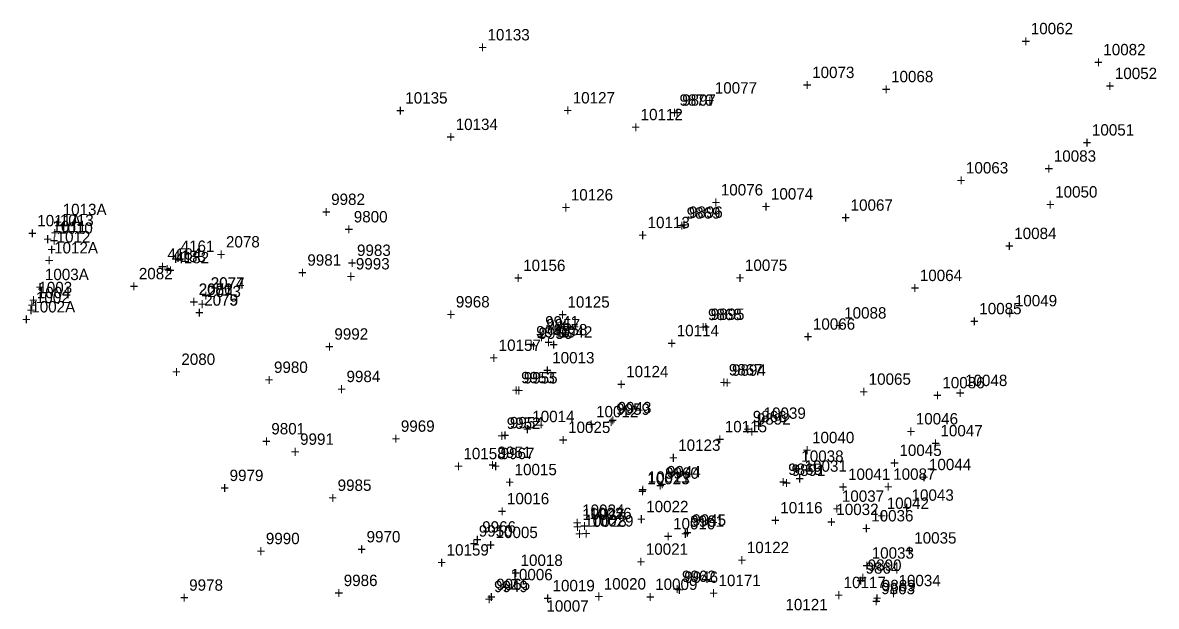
# Model space of a CAD drawing. Extents: x 1136220 to 1137808, y 528804 to 531215.
# Drawn here: x 1137114.7 to 1137364.2, y 528944.9 to 529073.3 of the extents above; entities that cross this region are included whole.
import ezdxf

# ---------------------------------------------------------------- set-up
doc = ezdxf.new("R2010")
doc.units = 0
for name, color, linetype in [('S_Annotation_Label', 7, 'Continuous'), ('S_Curb_Type_3', 7, 'Continuous'), ('S_Drainage_Culvert_Top', 7, 'Continuous'), ('S_Drainage_Invert', 7, 'Continuous'), ('S_Drainage_Sump', 7, 'Continuous'), ('S_Ground_Elevation', 7, 'Continuous'), ('S_Ground_LevelString', 7, 'Continuous'), ('S_Misc_MiscItems', 7, 'Continuous'), ('S_Property_ConcPad', 7, 'Continuous'), ('S_Roadway_Edge_Pavement', 7, 'Continuous'), ('S_Utilities_UG_Sanitary_MH', 7, 'Continuous'), ('S_Utilities_UG_Water_Gate', 7, 'Continuous'), ('S_Utilities_UG_Water_Line', 7, 'Continuous')]:
    doc.layers.add(name, color=color, linetype=linetype)

msp = doc.modelspace()

# ---------------------------------------------------------------- texts
at = {"layer": 'S_Annotation_Label'}
for s, p in [('9800', (1137187.58, 529029.39)), ('+', (1137185.52, 529026.64)), ('10088', (1137295.52, 529008.24)), ('+', (1137293.46, 529005.49)), ('9801', (1137169.43, 528982.76)), ('+', (1137167.37, 528980.01))]:
    msp.add_text(s, height=2.5, dxfattribs=at).set_placement(p)
at = {"layer": 'S_Curb_Type_3'}
for s, p in [('9897', (1137259.85, 529055.06)), ('+', (1137257.79, 529052.31)), ('9896', (1137261.36, 529030.4)), ('+', (1137259.29, 529027.65)), ('9895', (1137266.13, 529007.94)), ('9957', (1137229.96, 529005.67)), ('9958', (1137231.54, 529004.54)), ('+', (1137264.07, 529005.19)), ('+', (1137227.9, 529002.92)), ('9956', (1137228.25, 529003.77)), ('+', (1137226.18, 529001.02)), ('+', (1137229.48, 529001.79)), ('9894', (1137270.84, 528995.66)), ('9955', (1137225, 528993.96)), ('+', (1137268.78, 528992.91)), ('+', (1137222.94, 528991.21)), ('9959', (1137245.34, 528987.06)), ('9892', (1137276.3, 528984.9)), ('9954', (1137221.95, 528984.1)), ('+', (1137243.28, 528984.31)), ('+', (1137219.89, 528981.36)), ('+', (1137274.24, 528982.15)), ('9967', (1137219.9, 528977.32)), ('+', (1137217.84, 528974.57)), ('9960', (1137256.11, 528973.01)), ('9891', (1137283.93, 528973.63)), ('+', (1137254.05, 528970.26)), ('+', (1137281.87, 528970.88)), ('9961', (1137261.64, 528962.44)), ('9966', (1137215.85, 528961.16)), ('+', (1137213.79, 528958.41)), ('+', (1137259.58, 528959.69)), ('9890', (1137300.7, 528952.76)), ('9962', (1137259.82, 528950.3)), ('+', (1137298.63, 528950.01)), ('9965', (1137218.94, 528948.52)), ('+', (1137257.76, 528947.55)), ('9889', (1137303.82, 528948.27)), ('+', (1137216.88, 528945.77)), ('+', (1137301.76, 528945.52))]:
    msp.add_text(s, height=2.5, dxfattribs=at).set_placement(p)
at = {"layer": 'S_Drainage_Culvert_Top'}
for s, p in [('1013A', (1137123.51, 529030.99)), ('1011A', (1137117.91, 529028.53)), ('+', (1137121.45, 529028.24)), ('+', (1137115.85, 529025.78)), ('1012A', (1137121.62, 529022.57)), ('2078', (1137159.45, 529023.88)), ('+', (1137157.39, 529021.13)), ('+', (1137119.56, 529019.82)), ('1003A', (1137119.6, 529016.7)), ('2082', (1137140.27, 529016.88)), ('2077', (1137156.11, 529014.8)), ('+', (1137117.54, 529013.95)), ('+', (1137138.21, 529014.13)), ('2081', (1137153.47, 529013.43)), ('1002A', (1137116.6, 529009.59)), ('+', (1137151.41, 529010.68)), ('+', (1137154.05, 529012.05)), ('2079', (1137154.67, 529011.08)), ('+', (1137152.61, 529008.33)), ('+', (1137114.54, 529006.84)), ('2080', (1137149.63, 528998.05)), ('+', (1137147.57, 528995.3))]:
    msp.add_text(s, height=2.5, dxfattribs=at).set_placement(p)
at = {"layer": 'S_Drainage_Invert'}
for s, p in [('1011', (1137121.28, 529027.25)), ('1013', (1137122.89, 529028.63)), ('+', (1137120.83, 529025.88)), ('1012', (1137122.17, 529024.96)), ('+', (1137119.22, 529024.5)), ('+', (1137120.11, 529022.21)), ('2074', (1137156.08, 529014.83)), ('1003', (1137118.16, 529013.82)), ('2076', (1137153.44, 529013.47)), ('+', (1137116.1, 529011.07)), ('1002', (1137117.61, 529011.63)), ('+', (1137151.38, 529010.72)), ('+', (1137154.02, 529012.08)), ('2075', (1137154.65, 529011.07)), ('+', (1137115.55, 529008.88)), ('+', (1137152.59, 529008.32))]:
    msp.add_text(s, height=2.5, dxfattribs=at).set_placement(p)
at = {"layer": 'S_Drainage_Sump'}
for s, p in [('1010', (1137122.7, 529026.9)), ('+', (1137120.64, 529024.15)), ('1004', (1137117.82, 529012.72)), ('+', (1137115.76, 529009.97))]:
    msp.add_text(s, height=2.5, dxfattribs=at).set_placement(p)
at = {"layer": 'S_Ground_Elevation'}
for s, p in [('10062', (1137336.59, 529070.78)), ('+', (1137334.53, 529068.03)), ('10073', (1137288.47, 529061.14)), ('10068', (1137305.84, 529060.22)), ('10052', (1137355.1, 529060.92)), ('10077', (1137267.04, 529057.73)), ('+', (1137286.4, 529058.39)), ('+', (1137303.78, 529057.47)), ('+', (1137353.03, 529058.17)), ('+', (1137264.98, 529054.98)), ('10051', (1137350.05, 529048.49)), ('+', (1137347.99, 529045.74)), ('10063', (1137322.33, 529040.16)), ('+', (1137320.27, 529037.41)), ('10076', (1137268.37, 529035.32)), ('10074', (1137279.4, 529034.42)), ('10050', (1137341.96, 529034.86)), ('9982', (1137182.6, 529033.23)), ('+', (1137266.31, 529032.57)), ('10067', (1137296.94, 529031.96)), ('+', (1137180.54, 529030.48)), ('+', (1137277.34, 529031.67)), ('+', (1137339.9, 529032.11)), ('+', (1137294.88, 529029.21)), ('9983', (1137188.29, 529022.02)), ('9981', (1137177.36, 529019.87)), ('+', (1137186.23, 529019.27)), ('9993', (1137188.04, 529019.04)), ('10075', (1137273.68, 529018.73)), ('+', (1137175.3, 529017.12)), ('+', (1137185.98, 529016.29)), ('+', (1137271.62, 529015.98)), ('10064', (1137312.17, 529016.49)), ('+', (1137310.11, 529013.74)), ('9968', (1137210.05, 529010.68)), ('10049', (1137333.09, 529010.93)), ('+', (1137207.99, 529007.93)), ('+', (1137331.03, 529008.18)), ('10066', (1137288.64, 529005.79)), ('9992', (1137183.31, 529003.6)), ('+', (1137286.58, 529003.04)), ('+', (1137181.25, 529000.85)), ('10013', (1137231.26, 528998.38)), ('9980', (1137170.02, 528996.29)), ('+', (1137229.2, 528995.63)), ('+', (1137167.96, 528993.54)), ('9984', (1137185.98, 528994.26)), ('10065', (1137300.91, 528993.68)), ('10048', (1137322.13, 528993.39)), ('+', (1137183.92, 528991.51)), ('+', (1137298.85, 528990.93)), ('+', (1137320.07, 528990.64)), ('10014', (1137226.87, 528985.46)), ('10012', (1137240.91, 528986.52)), ('10039', (1137277.78, 528986.19)), ('10046', (1137311.28, 528984.95)), ('9969', (1137197.94, 528983.34)), ('9952', (1137221.24, 528983.98)), ('+', (1137224.81, 528982.71)), ('10025', (1137234.75, 528983.07)), ('+', (1137238.85, 528983.77)), ('+', (1137275.72, 528983.44)), ('10047', (1137316.71, 528982.33)), ('9991', (1137175.76, 528980.47)), ('+', (1137195.88, 528980.59)), ('+', (1137219.18, 528981.23)), ('+', (1137232.69, 528980.32)), ('10040', (1137288.45, 528980.83)), ('+', (1137309.22, 528982.2)), ('+', (1137173.7, 528977.72)), ('+', (1137286.39, 528978.08)), ('10045', (1137307.68, 528978.02)), ('+', (1137314.65, 528979.58)), ('10038', (1137286.09, 528976.73)), ('10031', (1137286.81, 528974.55)), ('+', (1137305.62, 528975.27)), ('10044', (1137314.18, 528974.89)), ('9979', (1137160.25, 528972.5)), ('10015', (1137222.98, 528973.78)), ('10011', (1137252.29, 528972.14)), ('+', (1137284.03, 528973.98)), ('10041', (1137296.37, 528972.75)), ('9985', (1137184.03, 528970.34)), ('+', (1137220.92, 528971.03)), ('10023', (1137252.19, 528971.79)), ('+', (1137284.75, 528971.8)), ('+', (1137294.31, 528970)), ('+', (1137312.12, 528972.14)), ('+', (1137158.19, 528969.75)), ('+', (1137181.97, 528967.59)), ('10016', (1137221.3, 528967.39)), ('+', (1137250.13, 528969.04)), ('+', (1137250.22, 528969.39)), ('10037', (1137295.01, 528967.94)), ('10043', (1137310.35, 528968.17)), ('10024', (1137237.84, 528964.85)), ('10022', (1137251.95, 528965.65)), ('+', (1137292.94, 528965.19)), ('10032', (1137293.79, 528965.02)), ('10042', (1137304.88, 528966.38)), ('+', (1137308.29, 528965.42)), ('+', (1137219.24, 528964.64)), ('+', (1137249.89, 528962.9)), ('10036', (1137301.47, 528963.62)), ('+', (1137302.82, 528963.63)), ('10005', (1137218.79, 528959.96)), ('+', (1137235.77, 528962.1)), ('10010', (1137257.86, 528961.87)), ('+', (1137291.73, 528962.27)), ('+', (1137299.41, 528960.87)), ('9990', (1137168.23, 528958.62)), ('9970', (1137190.4, 528959.01)), ('+', (1137255.8, 528959.12)), ('10035', (1137310.94, 528958.74)), ('+', (1137166.17, 528955.87)), ('+', (1137188.34, 528956.26)), ('+', (1137216.73, 528957.21)), ('10021', (1137251.86, 528956.29)), ('10033', (1137301.58, 528955.43)), ('+', (1137308.88, 528955.99)), ('10018', (1137224.29, 528953.83)), ('+', (1137249.8, 528953.54)), ('+', (1137299.52, 528952.68)), ('10006', (1137222.07, 528950.67)), ('+', (1137222.23, 528951.08)), ('9978', (1137151.35, 528948.38)), ('9986', (1137185.37, 528949.4)), ('+', (1137220.01, 528947.92)), ('10019', (1137231.33, 528948.25)), ('10020', (1137242.6, 528948.64)), ('10009', (1137253.92, 528948.55)), ('10034', (1137307.47, 528949.37)), ('+', (1137149.29, 528945.63)), ('+', (1137183.31, 528946.65)), ('+', (1137229.27, 528945.5)), ('+', (1137240.54, 528945.89)), ('+', (1137251.86, 528945.8)), ('+', (1137305.41, 528946.62)), ('10007', (1137229.98, 528943.77))]:
    msp.add_text(s, height=2.5, dxfattribs=at).set_placement(p)
at = {"layer": 'S_Ground_LevelString'}
for s, p in [('10133', (1137217.01, 529069.42)), ('+', (1137214.95, 529066.67)), ('10135', (1137198.92, 529055.53)), ('10127', (1137235.77, 529055.56)), ('+', (1137196.86, 529052.78)), ('+', (1137233.71, 529052.81)), ('10112', (1137250.72, 529051.87)), ('10134', (1137210.01, 529049.71)), ('+', (1137248.66, 529049.12)), ('+', (1137207.95, 529046.96)), ('10126', (1137235.35, 529034.21)), ('+', (1137233.29, 529031.46)), ('10113', (1137252.25, 529028.13)), ('+', (1137250.19, 529025.38)), ('10156', (1137224.86, 529018.69)), ('+', (1137222.8, 529015.94)), ('10125', (1137234.61, 529010.64)), ('+', (1137232.55, 529007.89)), ('10114', (1137258.66, 529004.35)), ('10157', (1137219.47, 529001.13)), ('+', (1137256.6, 529001.6)), ('+', (1137217.41, 528998.38)), ('10124', (1137247.53, 528995.33)), ('+', (1137245.47, 528992.58)), ('10115', (1137269.24, 528983.22)), ('+', (1137267.18, 528980.47)), ('10158', (1137211.71, 528977.3)), ('10123', (1137258.99, 528979.14)), ('+', (1137256.93, 528976.39)), ('+', (1137209.65, 528974.55)), ('10116', (1137281.46, 528965.39)), ('+', (1137279.4, 528962.64)), ('10159', (1137208.01, 528956.11)), ('10122', (1137274.09, 528956.64)), ('+', (1137205.95, 528953.36)), ('+', (1137272.03, 528953.89)), ('10171', (1137267.86, 528949.39)), ('10117', (1137295.4, 528948.95)), ('+', (1137265.8, 528946.64)), ('+', (1137293.34, 528946.2)), ('10121', (1137282.59, 528944.08))]:
    msp.add_text(s, height=2.5, dxfattribs=at).set_placement(p)
at = {"layer": 'S_Misc_MiscItems'}
for s, p in [('10082', (1137352.56, 529066.15)), ('+', (1137350.5, 529063.4)), ('10083', (1137341.66, 529042.74)), ('+', (1137339.59, 529039.99)), ('10084', (1137332.95, 529025.73)), ('+', (1137330.89, 529022.98)), ('10085', (1137325.26, 529009.18)), ('+', (1137323.19, 529006.43)), ('10086', (1137317.13, 528992.89)), ('+', (1137315.07, 528990.14)), ('10087', (1137306.31, 528972.78)), ('+', (1137304.25, 528970.03))]:
    msp.add_text(s, height=2.5, dxfattribs=at).set_placement(p)
at = {"layer": 'S_Property_ConcPad'}
for s, p in [('10027', (1137237.89, 528963.96)), ('10028', (1137238.34, 528962.43)), ('10026', (1137239.44, 528964.14)), ('10029', (1137239.84, 528962.49)), ('+', (1137235.83, 528961.21)), ('+', (1137237.38, 528961.39)), ('+', (1137236.28, 528959.68)), ('+', (1137237.77, 528959.74)), ('9863', (1137303.67, 528947.6)), ('+', (1137301.61, 528944.85))]:
    msp.add_text(s, height=2.5, dxfattribs=at).set_placement(p)
at = {"layer": 'S_Roadway_Edge_Pavement'}
for s, p in [('9870', (1137259.27, 529055.06)), ('+', (1137257.21, 529052.31)), ('9869', (1137260.85, 529030.22)), ('+', (1137258.79, 529027.47)), ('9868', (1137265.54, 529007.9)), ('9941', (1137229.71, 529006.28)), ('+', (1137263.48, 529005.15)), ('+', (1137227.65, 529003.53)), ('9940', (1137227.72, 529004.1)), ('9942', (1137232.66, 529004.04)), ('+', (1137225.66, 529001.35)), ('+', (1137230.6, 529001.29)), ('9867', (1137270.12, 528995.73)), ('9953', (1137224.41, 528994.02)), ('+', (1137268.06, 528992.98)), ('+', (1137222.35, 528991.27)), ('9943', (1137245.66, 528987.41)), ('9866', (1137275.4, 528985.45)), ('+', (1137243.6, 528984.66)), ('+', (1137273.34, 528982.7)), ('9951', (1137219.21, 528977.58)), ('+', (1137217.15, 528974.83)), ('9944', (1137256.52, 528973.32)), ('9865', (1137283.19, 528973.85)), ('+', (1137254.46, 528970.57)), ('+', (1137281.13, 528971.1)), ('9945', (1137262.08, 528962.69)), ('9950', (1137215.1, 528960.27)), ('+', (1137213.04, 528957.52)), ('+', (1137260.02, 528959.94)), ('9864', (1137300.23, 528952.12)), ('9946', (1137260.32, 528950.11)), ('9949', (1137218.46, 528948.07)), ('+', (1137298.17, 528949.37)), ('+', (1137216.4, 528945.32)), ('+', (1137258.26, 528947.36))]:
    msp.add_text(s, height=2.5, dxfattribs=at).set_placement(p)
at = {"layer": 'S_Utilities_UG_Sanitary_MH'}
for s, p in [('2073', (1137155.29, 529012.95)), ('+', (1137153.23, 529010.2))]:
    msp.add_text(s, height=2.5, dxfattribs=at).set_placement(p)
at = {"layer": 'S_Utilities_UG_Water_Gate'}
for s, p in [('4161', (1137149.47, 529022.9)), ('4184', (1137146.56, 529021.2)), ('+', (1137147.41, 529020.15)), ('+', (1137144.5, 529018.45))]:
    msp.add_text(s, height=2.5, dxfattribs=at).set_placement(p)
at = {"layer": 'S_Utilities_UG_Water_Line'}
for s, p in [('4183', (1137147.59, 529020.65)), ('4182', (1137148.3, 529020.4)), ('+', (1137145.53, 529017.9)), ('+', (1137146.24, 529017.65))]:
    msp.add_text(s, height=2.5, dxfattribs=at).set_placement(p)

doc.saveas('drawing.dxf')
